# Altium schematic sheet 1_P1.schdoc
size 307 x 218 mm; Symbol: Drawing-Symbol_A4; Device: Drawing-Symbol_A4; @Project Name: LED tower pcb; @Page Count: 1; @Update Date: 2025-07-07; @Create Date: 2025-07-06; @Schematic Name: Schematic2; @Page No: 1; @Page Name: P1; Company: EasyEDA.com; Version: V1.0; Page Size: A4; @Create Time: 21:33:25; @Update Time: 23:45:07; Width: 1170; Height: 825; Region Start: 1; X Region Count: 6; Y Region Count: 4; Blade Width: 10; Title Block Position: 3; @Board Name: Board2
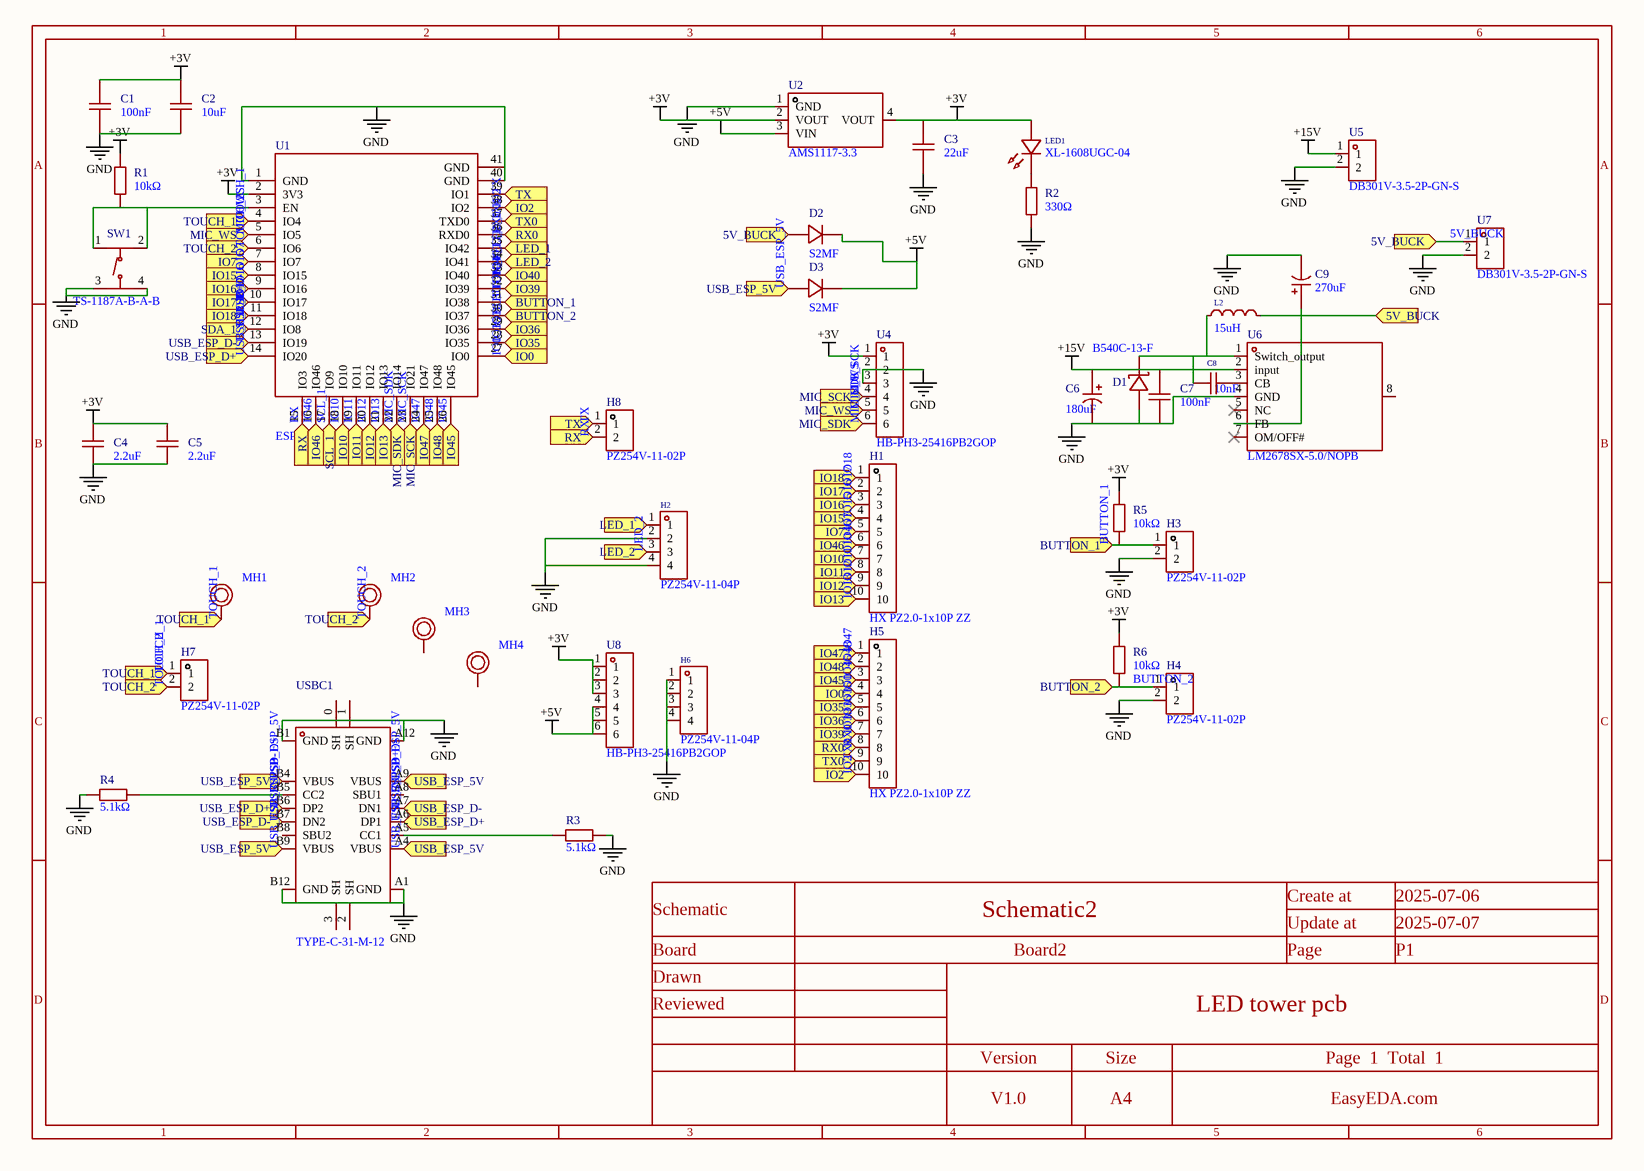
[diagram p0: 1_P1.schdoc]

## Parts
C1  100nF  [C0603]
C2  10uF  [C0603]
C3  22uF  [C0603]
C4  2.2uF  [C0805]
C5  2.2uF  [C0805]
C6  180uF  [CAP-SMD_BD10.0-L10.3-W10.3-FD]
C7  100nF  [C0603]
C8  10nF  [C0603]
C9  270uF  [CAP-SMD_BD10.0-L10.3-W10.3-FD-1]
D1  B540C-13-F  [SMC_L7.1-W6.2-LS8.1-RD]
D2  S2MF  [SMAF_L3.5-W2.6-LS4.7-RD]
D3  S2MF  [SMAF_L3.5-W2.6-LS4.7-RD]
H1  HX PZ2.0-1x10P ZZ  [HDR-TH_10P-P2.00-V-M-1]
H2  PZ254V-11-04P  [HDR-TH_4P-P2.54-V-M]
H3  PZ254V-11-02P  [HDR-TH_2P-P2.54-V-M]
H4  PZ254V-11-02P  [HDR-TH_2P-P2.54-V-M]
H5  HX PZ2.0-1x10P ZZ  [HDR-TH_10P-P2.00-V-M-1]
H6  PZ254V-11-04P  [HDR-TH_4P-P2.54-V-M]
H7  PZ254V-11-02P  [HDR-TH_2P-P2.54-V-M]
H8  PZ254V-11-02P  [HDR-TH_2P-P2.54-V-M]
L2  15uH  [IND-SMD_L12.0-W12.0_SLH1207S100MTT]
LED1  XL-1608UGC-04  [LED0603-RD_GREEN]
MH1  (no value)  [M3_Hole]
MH2  (no value)  [M3_Hole]
MH3  (no value)  [M3_Hole]
MH4  (no value)  [M3_Hole]
R1  10kΩ  [R0603]
R2  330Ω  [R0603]
R3  5.1kΩ  [R0603]
R4  5.1kΩ  [R0603]
R5  10kΩ  [R0603]
R6  10kΩ  [R0603]
SW1  TS-1187A-B-A-B  [SW-SMD_4P-L5.1-W5.1-P3.70-LS6.5-TL_H1.5]
U1  ESP32-S3-WROOM-1U-N16R2  [WIRELM-SMD_ESP32-S3-WROOM-1U]
U2  AMS1117-3.3  [SOT-223-3_L6.5-W3.4-P2.30-LS7.0-BR]
U4  HB-PH3-25416PB2GOP  [HDR-TH_6P-P2.54-V-M]
U5  DB301V-3.5-2P-GN-S  [CONN-TH_DB301V-3.5-2P-GN]
U6  LM2678SX-5.0/NOPB  [TO-263-7_L10.2-W8.6-P1.27-LS14.4-TL]
U7  DB301V-3.5-2P-GN-S  [CONN-TH_DB301V-3.5-2P-GN]
U8  HB-PH3-25416PB2GOP  [HDR-TH_6P-P2.54-V-M]
USBC1  TYPE-C-31-M-12  [USB-C_SMD-TYPE-C-31-M-12]

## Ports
5V_BUCK (in), BUTTON_1 (in), BUTTON_2 (in), IO0 (in), IO2 (in), IO7 (in), IO10 (in), IO11 (in), IO12 (in), IO13 (in), IO15 (in), IO16 (in), IO17 (in), IO18 (in), IO35 (in), IO36 (in), IO39 (in), IO40 (in), IO45 (in), IO46 (in), IO47 (in), IO48 (in), LED_1 (in), LED_2 (in), MIC_SCK (in), MIC_SDK (in), MIC_WS (in), RX0 (in), RX (in), SCL_1 (in), SDA_1 (in), TOUCH_1 (in), TOUCH_2 (in), TX0 (in), TX (in), USB_ESP_5V (in), USB_ESP_D+ (in), USB_ESP_D- (in)

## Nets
+3V: C1.2 C2.2 C3.2 C4.2 C5.2 LED1.2(A) R1.2 R5.2 R6.2 U1.2(3V3) U2.2(VOUT) U2.4(VOUT) U4.1 U8.1 U8.2 U8.3
+5V: D2.1(C) D3.1(C) U2.3(VIN) U8.4 U8.5 U8.6
+15V: C6.1 C7.2 U5.1 U6.2(input)
GND: C1.1 C2.1 C3.1 C4.1 C5.1 C6.2 C7.1 C9.2 D1.2(A) H2.2 H2.4 H3.2 H4.2 H6.1 H6.2 H6.3 H6.4 R2.1 R3.2 R4.1 SW1.3(C) SW1.4(D) U1.1(GND) U1.40(GND) U1.41(GND) U2.1(GND) U4.2 U4.3 U5.2 U6.4(GND) U7.2 USBC1.A1(GND) USBC1.A12(GND) USBC1.B1(GND) USBC1.B12(GND)
5V_BUCK: C9.1 D2.2(A) L2.2 U6.6(FB) U7.1 ; port 5V_BUCK
BUTTON_1: H3.1 R5.1 U1.31(IO38) ; port BUTTON_1
BUTTON_2: H4.1 R6.1 U1.30(IO37) ; port BUTTON_2
IO0: H5.4 U1.27(IO0) ; port IO0
IO2: H5.10 U1.38(IO2) ; port IO2
IO7: H1.5 U1.7(IO7) ; port IO7
IO10: H1.7 U1.18(IO10) ; port IO10
IO11: H1.8 U1.19(IO11) ; port IO11
IO12: H1.9 U1.20(IO12) ; port IO12
IO13: H1.10 U1.21(IO13) ; port IO13
IO15: H1.4 U1.8(IO15) ; port IO15
IO16: H1.3 U1.9(IO16) ; port IO16
IO17: H1.2 U1.10(IO17) ; port IO17
IO18: H1.1 U1.11(IO18) ; port IO18
IO35: H5.5 U1.28(IO35) ; port IO35
IO36: H5.6 U1.29(IO36) ; port IO36
IO39: H5.7 U1.32(IO39) ; port IO39
IO40: U1.33(IO40) ; port IO40
IO45: H5.3 U1.26(IO45) ; port IO45
IO46: H1.6 U1.16(IO46) ; port IO46
IO47: H5.1 U1.24(IO47) ; port IO47
IO48: H5.2 U1.25(IO48) ; port IO48
LED_1: H2.1 U1.35(IO42) ; port LED_1
LED_2: H2.3 U1.34(IO41) ; port LED_2
MIC_SCK: U1.23(IO21) U4.4 ; port MIC_SCK
MIC_SDK: U1.22(IO14) U4.6 ; port MIC_SDK
MIC_WS: U1.5(IO5) U4.5 ; port MIC_WS
RX: H8.2 U1.15(IO3) ; port RX
RX0: H5.8 U1.36(RXD0) ; port RX0
SCL_1: U1.17(IO9) ; port SCL_1
SDA_1: U1.12(IO8) ; port SDA_1
TOUCH_1: H7.1 MH1.1 U1.4(IO4) ; port TOUCH_1
TOUCH_2: H7.2 MH2.1 U1.6(IO6) ; port TOUCH_2
TX: H8.1 U1.39(IO1) ; port TX
TX0: H5.9 U1.37(TXD0) ; port TX0
USB_ESP_5V: D3.2(A) USBC1.A4(VBUS) USBC1.A9(VBUS) USBC1.B4(VBUS) USBC1.B9(VBUS) ; port USB_ESP_5V
USB_ESP_D+: U1.14(IO20) USBC1.A6(DP1) USBC1.B6(DP2) ; port USB_ESP_D+
USB_ESP_D-: U1.13(IO19) USBC1.A7(DN1) USBC1.B7(DN2) ; port USB_ESP_D-
NetC8_1: C8.1 D1.1(K) L2.1 U6.1(Switch_output)
NetC8_2: C8.2 U6.3(CB)
NetLED1_1: LED1.1(K) R2.2
NetR1_1: R1.1 SW1.1(A) SW1.2(B) U1.3(EN)
NetR3_1: R3.1 USBC1.A5(CC1)
NetR4_2: R4.2 USBC1.B5(CC2)

Not connected (* = marked no-connect by the designer): MH3 1; MH4 1; U6 5(NC)* 7(OM/OFF#)* 8; USBC1 0(SH) 1(SH) 2(SH) 3(SH) A8(SBU1) B8(SBU2)

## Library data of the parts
C1 C7 = CC0603KRX7R9BB104: Manufacturer: YAGEO(国巨); Add into BOM: yes; Tolerance: ±10%; Voltage Rating: 50V; Temperature Coefficient: X7R
C2 = CL10A106KP8NNNC: Manufacturer: SAMSUNG(三星); Add into BOM: yes; Tolerance: ±10%
C3 = CL10A226MP8NUNE: Manufacturer: SAMSUNG(三星); Add into BOM: yes; Tolerance: ±20%
C4 C5 = CL21B225KAFNNNE: Manufacturer: SAMSUNG(三星); Add into BOM: yes; Tolerance: ±10%
C6 = VMME1001H181MV: Manufacturer: Ymin(永铭); Add into BOM: yes; Tolerance: ±20%; Voltage Rating: 50V
C8 = CC0603KRX7R9BB103: Manufacturer: YAGEO(国巨); Add into BOM: yes; Tolerance: ±10%
C9 = RVT1H271M1010: Manufacturer: ROQANG(容强); Add into BOM: yes; Tolerance: ±20%; Voltage Rating: 50V
D1 = B540C-13-F: Manufacturer: DIODES(美台); Add into BOM: yes; Forward Voltage (Vf@If): 550mV@5A; Reverse Voltage (Vr): 40V; Average Rectified Current (Io): 5A; Reverse Leakage Current (Ir): 500uA@40V
D2 D3 = S2MF_C908416: Manufacturer: GOODWORK(固得沃克); Add into BOM: yes; Diode Configuration: Independent Type; Voltage - Forward(Vf@If): 1.1V@2A; Voltage - DC Reverse(Vr): 1kV; Current - Rectified: 2A; Reverse Leakage Current (Ir): 5uA@1kV
H1 H5 = HX PZ2.0-1x10P ZZ: Manufacturer: hanxia(韩下); Add into BOM: yes; Pin Structure: 1x10P; Pitch: 2mm; Circluar Pins/Square Pins: Policy; Current Rating: 1.5A
H2 H6 = PZ254V-11-04P: Manufacturer: XFCN(兴飞); Symbol: PZ254V-11-04P_C2691448; Add into BOM: yes; Pin Structure: 1x4P; Pitch: 2.54mm; Circluar Pins/Square Pins: Square Pins; Current Rating (Max): 3A; Voltage Rating (Max): 250V
H3 H4 H7 H8 = PZ254V-11-02P: Manufacturer: XFCN(兴飞); Add into BOM: yes; Pin Structure: 1x2P; Pitch: 2.54mm; Circluar Pins/Square Pins: Policy
L2 = MSS1210-334KED: Manufacturer: Coilcraft(线艺); Manufacturer Part: MSS1210-153MED; Add into BOM: yes; Tolerance: ±10%
LED1 = XL-1608UGC-04: Manufacturer: XINGLIGHT(成兴光); Add into BOM: yes; Emitted Color: Emerald; Power Dissipation: 80mW; Forward Current: 25mA; Dominant Wavelength: 516nm~525nm; Peak Wavelength: 534nm; Diode Configuration: 独立二极管; Lens Color: 无色透明透镜; Viewing Angle: 120°; Mounting Sytle: Positive post
MH1-MH4 = M3_Hole: Add into BOM: no; Convert to PCB: yes
R1 R5 R6 = RC0603FR-0710KL: Manufacturer: YAGEO(国巨); Add into BOM: yes; Tolerance: ±1%; Temperature Coefficient: ±100ppm/℃
R2 = RC0603FR-07330RL: Manufacturer: YAGEO(国巨); Add into BOM: yes; Tolerance: ±1%; Temperature Coefficient: ±100ppm/℃
R3 R4 = RC0603FR-075K1L: Manufacturer: YAGEO(国巨); Add into BOM: yes; Tolerance: ±1%; Power(Watts): 100mW; Voltage-Supply(Max): 75V; Temperature Coefficient: ±100ppm/℃
SW1 = TS-1187A-B-A-B: Manufacturer: XKB Connectivity(中国星坤); Add into BOM: yes; Circuit: SPST; Actuator Style: Round Button; Operating Force: 160gf; Switch Length: 5.1mm; Switch Height: 1.5mm; Strike Gundam: 不带; Contact Current: 50mA; Voltage Rating (DC): 12V; Actuator/Cap Color: 金色; With Lamp: No; Mechanical Life: 10万次
U1 = ESP32-S3-WROOM-1U-N16R2: Manufacturer: ESPRESSIF(乐鑫); Add into BOM: yes
U2 = AMS1117-3.3_C6186: Manufacturer: AMS; Add into BOM: yes; Output Type: Fixed; Voltage - Supply: 16V; Output Voltage: 3.3V; Output Current: 1A; Power Supply Rejection Ratio (PSRR): 72dB@(120Hz); Voltage Dropout: 1.1V@(800mA); standby current: 5mA; Output Configuration: Positive; Number of Outputs: 1
U4 U8 = HB-PH3-25416PB2GOP: Manufacturer: HANBO(汉博); Add into BOM: yes; Pin Structure: 1x6P; Pitch: 2.54mm; Circluar Pins/Square Pins: Policy; Current Rating: 3A; Voltage Rating (Max): 250V
U5 U7 = DB301V-3.5-2P-GN-S: Manufacturer: DORABO(地博电气); Add into BOM: yes; Number of Positions or Pins: 1x2P; Pitch: 3.5mm; Number of PINs Per Row: 2; Screw Specification: M2; Current Rating: 7A; Voltage Rating (Max): 300V
U6 = LM2678SX-5.0/NOPB: Manufacturer: TI(德州仪器); Add into BOM: yes; Function: Step-down type; Output Type: Fixed; Voltage - Supply: 8V~40V; Output Voltage: 5V; Output Current: 5A; Frequency - Switching: 260kHz; Synchronous Rectifier: NONE; Number of Outputs: 1; Topology: Step-down; Switch tube (built-in/external): Built-in
USBC1 = TYPE-C-31-M-12: Manufacturer: 韩国韩荣; Add into BOM: yes; Connector Type: Type-C; Gender: Female; Number of Contacts: 16P; Number of Ports: 1; Current Rating - Power (Max): 5A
